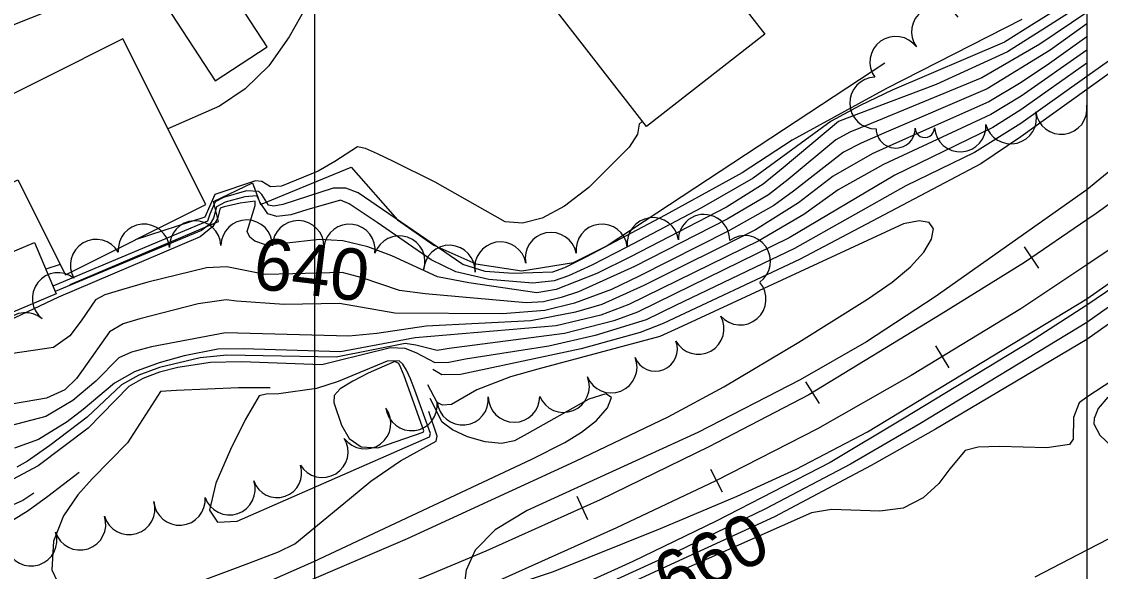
# Model space of a CAD drawing. Extents: x 79600 to 91800, y 75600 to 84400.
# Drawn here: x 84586.1 to 85005.3, y 82025.8 to 82239.4 of the extents above; entities that cross this region are included whole.
import ezdxf

# ---------------------------------------------------------------- set-up
doc = ezdxf.new("R2010")
doc.units = 0
for name, color, linetype in [('084-085$0$BLDG', 7, 'Continuous'), ('084-085$0$GRID', 7, 'Continuous'), ('084-085$0$INDEX', 7, 'Continuous'), ('084-085$0$INDXLBL', 7, 'Continuous'), ('084-085$0$INTER', 7, 'Continuous'), ('084-085$0$RR', 7, 'Continuous'), ('084-085$0$TREES', 7, 'Continuous'), ('084-085$0$WALL', 7, 'Continuous'), ('084-090$0$GRID', 7, 'Continuous'), ('084-090$0$INDEX', 7, 'Continuous'), ('084-090$0$INTER', 7, 'Continuous'), ('084-090$0$RR', 7, 'Continuous'), ('084-090$0$TI_BORDER', 7, 'Continuous')]:
    doc.layers.add(name, color=color, linetype=linetype)

# ---------------------------------------------------------------- blocks, each defined once
blk = doc.blocks.new('084-085$0$RRTICK100')
blk.add_line((0, -5), (0, 5))

msp = doc.modelspace()

# ---------------------------------------------------------------- linework, layer by layer
at = {"layer": '084-085$0$BLDG'}
for points in [[(84754.83, 82302.45), (84736.94, 82325.42), (84776.07, 82355.91), (84794.19, 82332.66), (84796.83, 82334.72), (84874.91, 82234.5), (84828.93, 82198.67), (84750.62, 82299.18)], [(84623.19, 82274.72), (84661.24, 82216.4), (84681.47, 82229.6), (84643.42, 82287.92)], [(84547.69, 82159.46), (84584.61, 82177.94), (84603.11, 82140.97), (84657.66, 82168.27), (84625.45, 82232.64), (84533.98, 82186.87)], [(84599.51, 82133.6), (84524.45, 82101.87), (84516.01, 82121.83), (84591.07, 82153.57)]]:
    msp.add_lwpolyline(points, close=True, dxfattribs=at)
at = {"layer": '084-085$0$GRID'}
msp.add_line((85000, 84000), (85000, 80000), dxfattribs=at)
at = {"layer": '084-085$0$INDEX'}
for points in [[(84746.45, 82313.21), (84746.45, 82313.2), (84737.01, 82305.25), (84731.59, 82300.5), (84718.8, 82276.75), (84702.14, 82254.71), (84696.67, 82245.14), (84690.01, 82233.45), (84682.11, 82222.15), (84673, 82213.21), (84663, 82206.51), (84642.93, 82197.71)], [(85000, 82242.85), (84981.79, 82230.57), (84959.22, 82217.46), (84916.24, 82199.75), (84907.9, 82196.35), (84902.43, 82193.43), (84883.98, 82178.03), (84876.3, 82172.03), (84860.28, 82162.66), (84824.22, 82144.17), (84802.53, 82134.39), (84795.8, 82132.2), (84788.84, 82130.47), (84782.1, 82130.05), (84742.9, 82133.65), (84732.93, 82134.96), (84718.47, 82139.85), (84710.67, 82141.87), (84691.52, 82141.37), (84680.76, 82141.14), (84665.85, 82144.08), (84657.98, 82143.73), (84635.08, 82138.2), (84624.87, 82135.16), (84618.44, 82133.18), (84614.8, 82131.32), (84609.24, 82123.12), (84604.89, 82117.32), (84598.51, 82112.76), (84565.85, 82107.91)], [(85000, 82218.08), (84974.34, 82199.82), (84956.39, 82188.55), (84929.69, 82175.58), (84886.38, 82151.17), (84840.15, 82129.09), (84828.71, 82123.48), (84809.01, 82117.46), (84791.01, 82113.27), (84758.59, 82108.22), (84752.08, 82106.93), (84746.81, 82106.8), (84739.42, 82110.65), (84735.19, 82112.41), (84729.39, 82112.65), (84708.45, 82107.46), (84702.69, 82106.06), (84671.56, 82107.15), (84659.5, 82106.89), (84646.83, 82104.92), (84639.73, 82103.11), (84633.16, 82100.68), (84627.77, 82097.64), (84611.97, 82081.38), (84592.48, 82066.79), (84582.58, 82061.41)], [(85000, 82093.46), (84997.01, 82091.2), (84994.76, 82085.62), (84994.62, 82077.18), (84993.3, 82075.05), (84984.45, 82073.79), (84966.01, 82074.33), (84957.75, 82074.09), (84952.71, 82072.71), (84946.79, 82065.65), (84942.43, 82059.97), (84936.35, 82054.29), (84928.65, 82050.3), (84919.57, 82049.12), (84900.79, 82049.76), (84892.96, 82048.47), (84791.55, 82003.63)]]:
    msp.add_lwpolyline(points, dxfattribs=at)
msp.add_lwpolyline([(84744.97, 82079.34), (84738.89, 82096.16), (84737.17, 82100.54), (84735.67, 82103.92), (84734.25, 82106.24), (84732.75, 82107.59), (84728.09, 82107.43), (84709.09, 82099.59), (84700.69, 82096.88), (84686.03, 82094.79), (84681.16, 82094.58), (84678.4, 82093.98), (84672.9, 82084.67), (84667.2, 82073.17), (84661.54, 82060.05), (84659.09, 82049.55), (84662.2, 82044.91), (84669.84, 82045.28), (84744.59, 82078.09)], close=True, dxfattribs=at)
at = {"layer": '084-085$0$INTER'}
for p, q in [((84601.08, 82145.04), (84595.46, 82143.2)), ((84747.58, 82078.25), (84744.27, 82087.9))]:
    msp.add_line(p, q, dxfattribs=at)
for points in [[(84631.55, 82261.9), (84621.77, 82255.47), (84601.6, 82245.45), (84577.43, 82235.86), (84534.19, 82221.68), (84522.04, 82217.07), (84504.53, 82208.95), (84454.57, 82173.79), (84451.7, 82171.75)], [(85000, 82251.47), (84979.49, 82238.65), (84967.95, 82231.43), (84924.37, 82212.68), (84911.96, 82206.81), (84900.62, 82200.71), (84870.3, 82178.51), (84850.33, 82167.06), (84821.21, 82151.69), (84807.62, 82144.74), (84798.6, 82140.54), (84793.07, 82138.62), (84784.77, 82137.73), (84767.58, 82139.22), (84754.86, 82142.17), (84745.25, 82146.83), (84724.21, 82161.3), (84713.43, 82168.56), (84709.95, 82170.02), (84696.98, 82166.2), (84690.69, 82164.36), (84685.21, 82163.62), (84681.7, 82164.65), (84678.84, 82169.12), (84677.43, 82171.7), (84672.83, 82171.34), (84665.17, 82169.25), (84661.8, 82167.45), (84660.62, 82163), (84659.36, 82160.8), (84656.02, 82158.15), (84599.12, 82134.53)], [(85000, 82247.16), (84984.3, 82237.15), (84969.17, 82227.59), (84941.44, 82214.94), (84911.33, 82203.49), (84903.54, 82200.5), (84881.97, 82182.54), (84874.28, 82176.2), (84859.96, 82167.31), (84822.66, 82147.92), (84809.62, 82141.46), (84793.82, 82135.26), (84786.33, 82133.96), (84759.82, 82137.84), (84747.74, 82140.22), (84729.9, 82148.43), (84720.68, 82151.81), (84710.92, 82154.19), (84701.83, 82154.76), (84687.96, 82153.11), (84681.23, 82152.52), (84676.75, 82154.04), (84674.75, 82155.62), (84673.7, 82157.83), (84676.87, 82167.91), (84676.8, 82169.58), (84670.97, 82168.88), (84664.83, 82167.45), (84663.24, 82166.93), (84662.27, 82162.81), (84660.45, 82159.72), (84655.47, 82155.78), (84600.37, 82132.35), (84549.2, 82108.11)], [(85000, 82238.51), (84985.71, 82228.31), (84961.2, 82213.3), (84921.16, 82196.02), (84912.26, 82192.19), (84905.47, 82188.61), (84885.99, 82173.51), (84878.32, 82167.86), (84860.61, 82158.01), (84826.07, 82140.49), (84815.34, 82135.32), (84800.91, 82129.93), (84789.35, 82127.14), (84772.93, 82125.8), (84731.09, 82126.08), (84709.61, 82129.9), (84688.11, 82129.43), (84669.53, 82130.73), (84665.62, 82131.27), (84654.68, 82129.78), (84632, 82123.95), (84625.56, 82121.94), (84620.19, 82118.9), (84609.97, 82104.29), (84607.47, 82100.68), (84602.85, 82096.25), (84595.78, 82093.06), (84573.73, 82089.31)], [(84974.68, 82240.16), (84922.2, 82213.43), (84885.44, 82193.33), (84866.03, 82180.55), (84836.19, 82164.23), (84805.63, 82148.01), (84797.05, 82143.72), (84792.31, 82141.99), (84777.04, 82141.55), (84766.23, 82142.23), (84757.55, 82145.04), (84716.86, 82172.81), (84712.1, 82174.65), (84707.14, 82174.71), (84687.54, 82168.26), (84684.14, 82167.63), (84682.06, 82168.04), (84679.43, 82172.25), (84678.24, 82173.42), (84673.44, 82173.62), (84664.52, 82171.09), (84661.34, 82169.41), (84659.27, 82164.62), (84658.27, 82161.89), (84598.24, 82136.6)], [(85000, 82233.41), (84985.49, 82223.03), (84974.46, 82215.66), (84961.97, 82208.26), (84926.07, 82192.28), (84916.61, 82188.04), (84901.38, 82179.27), (84888, 82169), (84871.23, 82158.53), (84827.91, 82136.81), (84811.54, 82129.43), (84801.34, 82126.42), (84783.93, 82123.07), (84743.31, 82121.05), (84724.12, 82118.23), (84713.2, 82117.18), (84665.38, 82118.47), (84636.5, 82112.96), (84628.73, 82110.93), (84623.89, 82108.74), (84614.98, 82099.72), (84606.01, 82092.1), (84595.57, 82085.91), (84578.69, 82081.57)], [(85000, 82228.3), (84974.42, 82210.38), (84962.75, 82203.23), (84920.97, 82183.89), (84903.33, 82174.05), (84890.01, 82164.48), (84872.52, 82154.22), (84822.03, 82129.4), (84811.11, 82125.38), (84793.8, 82121.13), (84739.04, 82116.55), (84710.01, 82111.08), (84672.16, 82112.2), (84662.39, 82112.13), (84649.26, 82109.48), (84639.57, 82106.85), (84630.01, 82103.29), (84622.13, 82098.89), (84610.01, 82088.62), (84603.83, 82083.84), (84592.61, 82077.02), (84583.29, 82073.61)], [(85000, 82223.19), (84974.38, 82205.1), (84963.52, 82198.19), (84925.33, 82179.73), (84884.37, 82155.34), (84839.64, 82133.48), (84825.37, 82126.44), (84816.21, 82123.11), (84797.03, 82118.18), (84752.22, 82112.35), (84747.51, 82111.54), (84739.23, 82113.6), (84735.16, 82114.31), (84708.33, 82109.03), (84665.85, 82109.79), (84655.42, 82108.68), (84639.65, 82104.98), (84631.59, 82101.98), (84624.95, 82098.26), (84611.52, 82085.73), (84597.05, 82074.64), (84588.42, 82068.58), (84584.2, 82066.31)], [(85000, 82212.97), (84974.3, 82194.54), (84958.76, 82184.07), (84888.4, 82147), (84835.31, 82122.08), (84826.41, 82118.56), (84803.48, 82112.28), (84756.65, 82102.32), (84749.35, 82102.14), (84745.86, 82104.21)], [(84827.32, 82200.74), (84826.08, 82199.52), (84825.37, 82195.58), (84822.15, 82190.65), (84806.51, 82174.89), (84797.01, 82167.6), (84788.38, 82162.98), (84780.78, 82161.09), (84774.03, 82161.6), (84746.73, 82177.04), (84730.55, 82185.04), (84724.36, 82188.04), (84719.76, 82190.03), (84716.55, 82190.75), (84707.83, 82184.96), (84701.29, 82181.22), (84687.03, 82175.48), (84682.8, 82175.18), (84679.39, 82177.27), (84677.02, 82177.54), (84661.22, 82172.17), (84657.32, 82163.38), (84630.24, 82154.55)], [(85000, 82174.04), (84941.12, 82132.46), (84914.38, 82114.91), (84888.6, 82100.18), (84848.84, 82079.74), (84782.58, 82049.4), (84770.04, 82041.97), (84762.38, 82033.96), (84758.83, 82026.28), (84758.11, 82020.16), (84759.48, 82016.66), (84764.5, 82016.27), (84792.79, 82025.77), (84834.39, 82042.44), (84864.12, 82054.96), (84887.07, 82065.46), (84914.83, 82080.03), (85000, 82131.63)], [(84639.25, 81997.07), (84736.07, 82038.61), (84801.28, 82068.65), (84837.38, 82085.77), (84858.98, 82097.5), (84888.04, 82114.78), (84914.83, 82131.5), (84924.3, 82138.12), (84931.47, 82144.11), (84936.6, 82149.79), (84939.63, 82154.85), (84940.4, 82158.82), (84938.79, 82161.27), (84934.88, 82161.99), (84928.81, 82160.83), (84841.17, 82120.31), (84834.06, 82117.05), (84786.68, 82104.37), (84776.04, 82101.35), (84762.94, 82096.33), (84753.13, 82090.59), (84749.6, 82090.31), (84747.56, 82091.45), (84743.87, 82098.25)], [(85000, 82129.23), (84977.69, 82114.82), (84928.95, 82085.31), (84900.25, 82068.04), (84855.95, 82045.31), (84823.62, 82029.61), (84734.84, 81989.28), (84657.14, 81956.61), (84620.33, 81940.3), (84610.65, 81934.36), (84575.96, 81920.84), (84548.06, 81910.69)], [(85000, 82122.52), (84935.09, 82083.15), (84908.21, 82067.49), (84875.11, 82050.09), (84836.78, 82031.61), (84738.39, 81986.63), (84691.09, 81966.73), (84670.24, 81957.75), (84653.29, 81949.93), (84636.9, 81938.6), (84620.75, 81930.12), (84550.46, 81904.18)], [(85000, 82115.8), (84941.23, 82080.98), (84916.17, 82066.94), (84878.64, 82047.03), (84750.79, 81988.16), (84710.6, 81970.71), (84696.77, 81964.91), (84683.33, 81958.89), (84673.14, 81953.5), (84660.79, 81941.37), (84642.42, 81930.39), (84634.24, 81925.56), (84630.48, 81922.44), (84630.01, 81920.13), (84624.37, 81920.37), (84581.32, 81906.51), (84553.28, 81896.54)], [(84531.37, 81955.91), (84572.52, 81973.63), (84699.59, 82029.6), (84784.29, 82069.39), (84797.14, 82075.9), (84803.68, 82079.87), (84809.47, 82084.42), (84813.71, 82089.33), (84815.28, 82093.3), (84813.04, 82094.77), (84806.44, 82092.71), (84782.58, 82079.23), (84777.67, 82076.52), (84772.56, 82075.43), (84766.17, 82076.06), (84759.35, 82078.01), (84753.46, 82080.74), (84749.52, 82083.76), (84744.8, 82092.99)], [(84682.69, 82097.07), (84670.35, 82097.05), (84646.3, 82096.05), (84640.07, 82095.62), (84627.21, 82075.68), (84613.56, 82061.77), (84607.95, 82055.52), (84602.43, 82047.39), (84598.53, 82037.48), (84597.83, 82026.42), (84602.26, 82016.99), (84613.79, 82012.49), (84633.06, 82015.02), (84655.31, 82021.83), (84674.41, 82028.93), (84685.96, 82033.4), (84692.32, 82036.43), (84713.54, 82053.99), (84721.8, 82060.85), (84733.34, 82068.74), (84747.19, 82076.33), (84747.58, 82078.25)], [(84608.52, 82064.2), (84596.31, 82054.9), (84588.59, 82049.28), (84583.2, 82045.87), (84535.37, 82030.36), (84524.79, 82027.6), (84519.79, 82027.83), (84502.69, 82033.59)], [(84590.88, 82056.16), (84586.59, 82053.32), (84575.13, 82048.23), (84549.41, 82040.5), (84533.1, 82036.49), (84524.23, 82035.38), (84518.35, 82035.39), (84506.2, 82038.83), (84499.97, 82040.98)], [(85000, 82034.04), (84979.82, 82023.51)]]:
    msp.add_lwpolyline(points, dxfattribs=at)
msp.add_lwpolyline([(84742.37, 82080.44), (84734.69, 82101.73), (84733.44, 82104.89), (84732.63, 82106.49), (84731.16, 82107.26), (84720.75, 82102.81), (84714.76, 82099.73), (84709.92, 82096.7), (84707.57, 82094.12), (84707.36, 82091.4), (84710.39, 82082.58), (84713.4, 82077.46), (84718.06, 82074.12), (84724.54, 82073.82), (84742.12, 82079.91)], close=True, dxfattribs=at)
at = {"layer": '084-085$0$RR'}
for points in [[(85000, 82162.3), (84975.74, 82145.82), (84943.36, 82125.74), (84891.95, 82094.35), (84853.09, 82074.21), (84810.84, 82053.57), (84766.42, 82033.67), (84538.01, 81937.92)], [(85000, 82144.89), (84974.37, 82127.75), (84931.71, 82101.85), (84895.33, 82081.11), (84855.85, 82060.96), (84817.28, 82042.67), (84748.88, 82012.04), (84549.14, 81929.79), (84542.11, 81926.81)]]:
    msp.add_lwpolyline(points, dxfattribs=at)
at = {"layer": '084-085$0$TREES'}
for centre, radius, start, end in [((84941.88, 82235.33), 10, 35.6147, 215.6147), ((84925.67, 82223.62), 10, 36.0557, 216.0557), ((84917.84, 82207.74), 10, 91.4976, 271.4976), ((84970.46, 82201.87), 10, 194.0279, 14.0279), ((84990.08, 82205.57), 10, 187.3165, 7.3165), ((84950.78, 82198.78), 10, 183.8084, 3.8084), ((84925.71, 82197.87), 7.61, 180.9393, 0.9393), ((84937.06, 82198.05), 3.74, 180.9393, 0.9393), ((84653.57, 82151.99), 10, 2.5522, 182.5522), ((84673.55, 82152.32), 10, 359.3704, 179.3704), ((84693.55, 82152.07), 10, 359.2014, 179.2014), ((84831.36, 82153.23), 10, 7.5615, 187.5615), ((84851.27, 82154.45), 10, 359.4713, 179.4713), ((84633.61, 82150.7), 10, 4.85, 184.85), ((84713.47, 82150.65), 10, 352.6148, 172.6148), ((84791.79, 82147.49), 10, 11.2563, 191.2563), ((84811.52, 82150.68), 10, 7.0981, 187.0981), ((84615.04, 82144.77), 10, 30.5512, 210.5512), ((84732.85, 82146.12), 10, 341.096, 161.096), ((84772.14, 82143.79), 10, 10.0445, 190.0445), ((84867.07, 82146.22), 10, 305.4558, 125.4558), ((84752.3, 82142.47), 10, 357.6156, 177.6156), ((84600.26, 82131.81), 10, 51.9237, 231.9237), ((84865.32, 82131.52), 10, 220.9252, 40.9252), ((84587.65, 82116.29), 10, 49.9466, 229.9466), ((84849.01, 82120.12), 10, 208.9941, 28.9941), ((84832.37, 82112.06), 8.52, 202.1482, 22.1482), ((84815.21, 82105.08), 10, 202.1482, 22.1482), ((84796.69, 82097.54), 10, 202.1482, 22.1482), ((84737.6, 82090.43), 10, 187.0055, 7.0055), ((84757.48, 82092.64), 10, 185.7137, 5.7137), ((84777.43, 82093.7), 10, 180.3652, 0.3652), ((84719.58, 82083.33), 10, 215.9729, 35.9729), ((84702.95, 82072.25), 10, 211.3724, 31.3724), ((84685.38, 82063.98), 9.54, 198.724, 18.724), ((84666.87, 82057.71), 10, 198.724, 18.724), ((84627.88, 82050.04), 10, 196.667, 16.667), ((84647.43, 82053.7), 10, 184.5805, 4.5805), ((84608.8, 82044.07), 10, 198.0696, 18.0696), ((84589.78, 82037.86), 10, 198.0696, 18.0696)]:
    msp.add_arc(centre, radius, start, end, dxfattribs=at)
at = {"layer": '084-085$0$WALL'}
msp.add_lwpolyline([(84604.99, 82137.22), (84662.64, 82161.72), (84660.71, 82169.42), (84675.77, 82176.67), (84678.94, 82168.36), (84714.15, 82182.76), (84732.11, 82162.4), (84746.26, 82152.51), (84762.54, 82145.26), (84780.47, 82142.5), (84800.51, 82145.79), (84813.26, 82152.09), (84921.56, 82223.41)], dxfattribs=at)
at = {"layer": '084-090$0$GRID'}
msp.add_line((85000, 84000), (85000, 80000), dxfattribs=at)
at = {"layer": '084-090$0$INDEX'}
for points in [[(85246.39, 82404.37), (85224.48, 82390.93), (85193.73, 82368.28), (85166.04, 82346.44), (85111.65, 82297.15), (85000, 82218.08)], [(85032.89, 82114.9), (85000, 82093.46)]]:
    msp.add_lwpolyline(points, dxfattribs=at)
at = {"layer": '084-090$0$INTER'}
for points in [[(85250.24, 82404.69), (85228.72, 82388.39), (85200.87, 82368.76), (85161.87, 82339.55), (85114.58, 82296.72), (85103.55, 82287.37), (85000, 82212.97)], [(85117.6, 82273.68), (85051.74, 82216.46), (85000, 82174.04)], [(85000, 82131.63), (85025.96, 82149.89), (85077.82, 82190.26), (85096.39, 82205.17), (85113.15, 82217.92), (85121.65, 82223.59), (85129.52, 82227.7), (85136.33, 82229.8), (85142.22, 82231.36), (85147.49, 82234.27), (85167.84, 82261.22)], [(85096.16, 82190.58), (85000, 82122.52)], [(85043.55, 82158.73), (85000, 82129.23)], [(85055.76, 82155.35), (85000, 82115.8)], [(85008.15, 82093.52), (85004.39, 82089.01), (85002.83, 82085.14), (85002.71, 82083.15), (85005.08, 82078.72), (85009.81, 82074.13)], [(85021.32, 82045.02), (85000, 82034.04)]]:
    msp.add_lwpolyline(points, dxfattribs=at)
at = {"layer": '084-090$0$RR'}
for points in [[(86153.28, 83943.88), (85933.9, 83485.8), (85758.12, 83119.71), (85690.49, 82979.78), (85674.9, 82948.29), (85659.44, 82919.26), (85642.77, 82887.91), (85628.81, 82863.07), (85611.2, 82832.49), (85591.44, 82800.8), (85571.68, 82769.57), (85544.13, 82730.24), (85511.37, 82685.91), (85471.43, 82634.57), (85256.44, 82378.02), (85218.73, 82334.88), (85191.53, 82306.51), (85164.47, 82279.53), (85141.37, 82258.31), (85109.84, 82229.74), (85084.12, 82208.03), (85052.41, 82183.17), (85018.39, 82157.2), (85000, 82144.89)], [(85113.8, 82251.24), (85078.9, 82221.26), (85040.75, 82191.55), (85003.65, 82164.78), (85000, 82162.3)]]:
    msp.add_lwpolyline(points, dxfattribs=at)
at = {"layer": '084-090$0$TI_BORDER'}
msp.add_lwpolyline([(84700, 84300), (91700, 84300), (91700, 79700), (84700, 79700)], close=True, dxfattribs=at)

# ---------------------------------------------------------------- block references
at = {"layer": '084-085$0$RR'}
for p, rotation in [((84978.46, 82147.67), -145.81586535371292), ((84943.73, 82109.14), -148.7426820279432), ((84893.34, 82095.2), -148.5952807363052), ((84856.08, 82061.08), -152.9585885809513), ((84803.92, 82050.47), -155.87686806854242)]:
    msp.add_blockref('084-085$0$RRTICK100', p, dxfattribs=dict(at, rotation=rotation))

# ---------------------------------------------------------------- texts
at = {"layer": '084-085$0$INDXLBL'}
for s, rotation, p in [('640', 353.0915, (84675.45, 82135.82)), ('660', 25.8975, (84838.17, 82012.19))]:
    msp.add_text(s, height=20, rotation=rotation, dxfattribs=at).set_placement(p)

doc.saveas('drawing.dxf')
